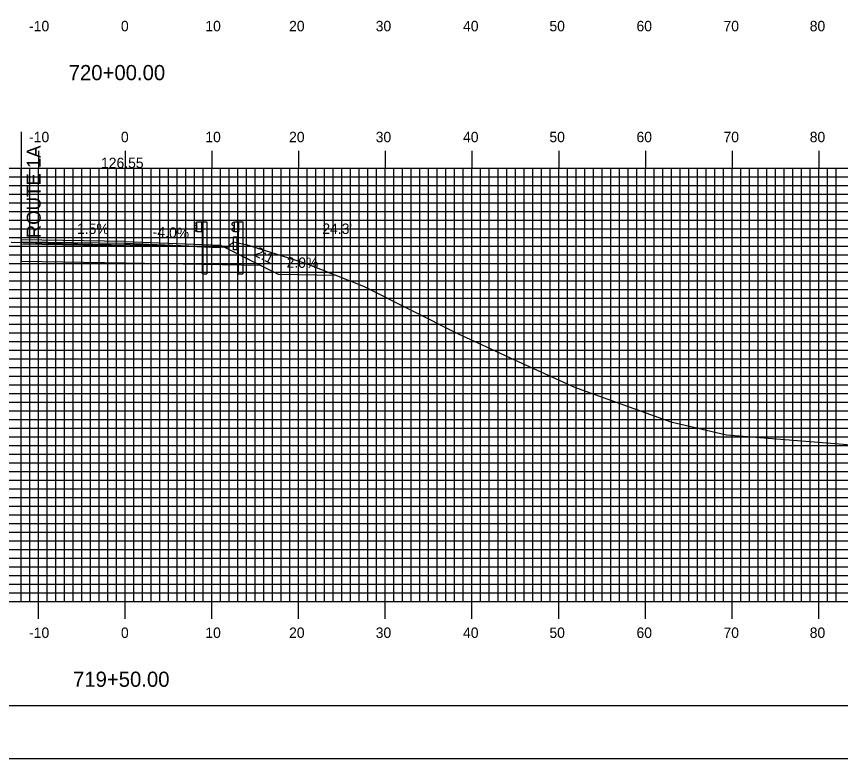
# Model space of a CAD drawing. Extents: x 858052 to 858395, y 364366 to 364586.
# Drawn here: x 858204.8 to 858299.9, y 364365.7 to 364451.3 of the extents above; entities that cross this region are included whole.
import ezdxf

# ---------------------------------------------------------------- set-up
doc = ezdxf.new("R2010")
doc.units = 0
for name, color, linetype in [('ANNOTATION', 7, 'Continuous'), ('BORDER', 7, 'Continuous'), ('D_Guardrail_Beam_Lt', 7, 'Continuous'), ('D_Roadway_Centerline', 7, 'Continuous'), ('D_Roadway_Centerline_Text', 7, 'Continuous'), ('D_Roadway_Edge_Shoulder', 7, 'Continuous'), ('D_Roadway_Edge_TW', 7, 'Continuous'), ('D_Roadway_Pavement', 7, 'Continuous'), ('D_Roadway_SlopeLines', 7, 'Continuous'), ('D_Roadway_SubGrade', 7, 'Continuous'), ('D_Text_Standard', 7, 'Continuous'), ('H_V ANNOTATION', 7, 'Continuous'), ('MAJOR', 7, 'Continuous'), ('MINOR', 7, 'Continuous'), ('PLOT BOUNDARY', 7, 'Continuous'), ('S_Curb_Type_1', 7, 'Continuous'), ('S_Guardrail_Beam', 7, 'Continuous'), ('S_Roadway_Centerline', 7, 'Continuous')]:
    doc.layers.add(name, color=color, linetype=linetype)

msp = doc.modelspace()

# ---------------------------------------------------------------- linework, layer by layer
at = {"layer": 'BORDER'}
msp.add_lwpolyline([(858067.762, 364371.787), (858387.762, 364371.787), (858387.762, 364581.787), (858067.762, 364581.787)], close=True, dxfattribs=at)
at = {"layer": 'D_Guardrail_Beam_Lt'}
for p, q in [((858225.542, 364427.494), (858225.399, 364427.394)), ((858225.399, 364427.251), (858225.594, 364427.115)), ((858225.594, 364426.916), (858225.399, 364426.78)), ((858225.632, 364427.516), (858225.558, 364427.501)), ((858225.628, 364427.051), (858225.628, 364426.98)), ((858225.632, 364427.599), (858226.32, 364427.599)), ((858225.632, 364426.432), (858225.632, 364427.599)), ((858226.153, 364427.599), (858226.153, 364426.432)), ((858226.257, 364427.599), (858226.257, 364426.432)), ((858226.32, 364427.599), (858226.791, 364427.599)), ((858226.32, 364427.599), (858226.32, 364426.432)), ((858226.791, 364427.599), (858226.791, 364421.599)), ((858225.399, 364426.637), (858225.542, 364426.537)), ((858225.558, 364426.53), (858225.632, 364426.516)), ((858226.32, 364426.432), (858225.632, 364426.432)), ((858226.299, 364421.599), (858226.299, 364426.432)), ((858226.299, 364421.599), (858226.791, 364421.599))]:
    msp.add_line(p, q, dxfattribs=at)
for centre, major_axis, start_param, end_param in [((858225.449, 364427.323), (-0.0877, 0), 5.323254, 7.243116), ((858225.449, 364426.708), (-0.0877, 0), 5.323254, 7.243116), ((858225.566, 364427.46), (-0.0417, 0), 4.907132, 5.323254), ((858225.549, 364427.051), (0.0789, 0), 0, 0.959931), ((858225.549, 364426.98), (0.0789, 0), 5.323254, 6.283185), ((858225.566, 364426.571), (-0.0417, 0), 0.959931, 1.376053)]:
    msp.add_ellipse(centre, major_axis=major_axis, ratio=0.995501, start_param=start_param, end_param=end_param, dxfattribs=at)
at = {"layer": 'D_Roadway_Centerline'}
for p, q in [((858217.362, 364425.336), (858205.362, 364425.516)), ((858217.362, 364425.086), (858205.362, 364425.266)), ((858217.362, 364424.839), (858205.362, 364425.019)), ((858217.362, 364422.836), (858205.362, 364423.016))]:
    msp.add_line(p, q, dxfattribs=at)
at = {"layer": 'D_Roadway_Edge_Shoulder'}
for points in [[(858217.362, 364425.336), (858228.362, 364424.896), (858228.362, 364424.646), (858217.362, 364425.086)], [(858217.362, 364425.336), (858225.362, 364425.016), (858225.362, 364425.016), (858228.362, 364424.896), (858228.362, 364424.646), (858217.362, 364425.086)]]:
    msp.add_lwpolyline(points, close=True, dxfattribs=at)
at = {"layer": 'D_Roadway_Edge_TW'}
msp.add_line((858205.362, 364425.544), (858205.362, 364425.294), dxfattribs=at)
at = {"layer": 'D_Roadway_Pavement'}
msp.add_line((858205.362, 364425.294), (858205.362, 364425.044), dxfattribs=at)
msp.add_lwpolyline([(858217.362, 364425.086), (858217.362, 364424.836)], dxfattribs=at)
msp.add_lwpolyline([(858217.362, 364425.086), (858217.362, 364424.836)], dxfattribs=at)
msp.add_lwpolyline([(858217.362, 364425.086), (858217.362, 364424.836)], dxfattribs=at)
msp.add_lwpolyline([(858217.362, 364425.086), (858217.362, 364424.836)], dxfattribs=at)
at = {"layer": 'D_Roadway_SlopeLines'}
for points in [[(858228.362, 364424.896), (858235.026, 364421.563)], [(858235.026, 364421.563), (858241.686, 364421.43)]]:
    msp.add_lwpolyline(points, dxfattribs=at)
at = {"layer": 'D_Roadway_SubGrade'}
for p, q in [((858205.362, 364438.001), (858205.362, 364423.112)), ((858205.362, 364437.973), (858205.362, 364423.016)), ((858205.362, 364425.044), (858205.362, 364423.112))]:
    msp.add_line(p, q, dxfattribs=at)
msp.add_lwpolyline([(858217.362, 364424.836), (858217.362, 364425.086), (858228.362, 364424.646), (858228.362, 364424.896), (858233.026, 364422.563), (858217.362, 364422.836)], close=True, dxfattribs=at)
at = {"layer": 'MAJOR'}
for p, q in [((858207.362, 364435.791), (858207.362, 364433.787)), ((858217.362, 364435.791), (858217.362, 364433.787)), ((858227.362, 364435.791), (858227.362, 364433.787)), ((858237.362, 364435.791), (858237.362, 364433.787)), ((858247.362, 364435.791), (858247.362, 364433.787)), ((858257.362, 364435.791), (858257.362, 364433.787)), ((858267.362, 364435.791), (858267.362, 364433.787)), ((858277.362, 364435.791), (858277.362, 364433.787)), ((858287.362, 364435.791), (858287.362, 364433.787)), ((858297.362, 364435.791), (858297.362, 364433.787)), ((858077.362, 364433.787), (858357.362, 364433.787)), ((858077.362, 364433.787), (858357.362, 364433.787)), ((858207.362, 364383.787), (858207.362, 364433.787)), ((858217.362, 364383.787), (858217.362, 364433.787)), ((858227.362, 364383.787), (858227.362, 364433.787)), ((858237.362, 364383.787), (858237.362, 364433.787)), ((858247.362, 364383.787), (858247.362, 364433.787)), ((858257.362, 364383.787), (858257.362, 364433.787)), ((858267.362, 364383.787), (858267.362, 364433.787)), ((858277.362, 364383.787), (858277.362, 364433.787)), ((858287.362, 364383.787), (858287.362, 364433.787)), ((858297.362, 364383.787), (858297.362, 364433.787)), ((858077.362, 364428.787), (858357.362, 364428.787)), ((858077.362, 364423.787), (858357.362, 364423.787)), ((858077.362, 364418.787), (858357.362, 364418.787)), ((858077.362, 364413.787), (858357.362, 364413.787)), ((858077.362, 364408.787), (858357.362, 364408.787)), ((858077.362, 364403.787), (858357.362, 364403.787)), ((858077.362, 364398.787), (858357.362, 364398.787)), ((858077.362, 364393.787), (858357.362, 364393.787)), ((858077.362, 364388.787), (858357.362, 364388.787)), ((858077.362, 364383.787), (858357.362, 364383.787)), ((858077.362, 364383.787), (858357.362, 364383.787)), ((858207.362, 364381.783), (858207.362, 364383.787)), ((858217.362, 364381.783), (858217.362, 364383.787)), ((858227.362, 364381.783), (858227.362, 364383.787)), ((858237.362, 364381.783), (858237.362, 364383.787)), ((858247.362, 364381.783), (858247.362, 364383.787)), ((858257.362, 364381.783), (858257.362, 364383.787)), ((858267.362, 364381.783), (858267.362, 364383.787)), ((858277.362, 364381.783), (858277.362, 364383.787)), ((858287.362, 364381.783), (858287.362, 364383.787)), ((858297.362, 364381.783), (858297.362, 364383.787))]:
    msp.add_line(p, q, dxfattribs=at)
at = {"layer": 'MINOR'}
for p, q in [((858205.362, 364383.787), (858205.362, 364433.787)), ((858206.362, 364383.787), (858206.362, 364433.787)), ((858208.362, 364383.787), (858208.362, 364433.787)), ((858209.362, 364383.787), (858209.362, 364433.787)), ((858210.362, 364383.787), (858210.362, 364433.787)), ((858211.362, 364383.787), (858211.362, 364433.787)), ((858212.362, 364383.787), (858212.362, 364433.787)), ((858213.362, 364383.787), (858213.362, 364433.787)), ((858214.362, 364383.787), (858214.362, 364433.787)), ((858215.362, 364383.787), (858215.362, 364433.787)), ((858216.362, 364383.787), (858216.362, 364433.787)), ((858218.362, 364383.787), (858218.362, 364433.787)), ((858219.362, 364383.787), (858219.362, 364433.787)), ((858220.362, 364383.787), (858220.362, 364433.787)), ((858221.362, 364383.787), (858221.362, 364433.787)), ((858222.362, 364383.787), (858222.362, 364433.787)), ((858223.362, 364383.787), (858223.362, 364433.787)), ((858224.362, 364383.787), (858224.362, 364433.787)), ((858225.362, 364383.787), (858225.362, 364433.787)), ((858226.362, 364383.787), (858226.362, 364433.787)), ((858228.362, 364383.787), (858228.362, 364433.787)), ((858229.362, 364383.787), (858229.362, 364433.787)), ((858230.362, 364383.787), (858230.362, 364433.787)), ((858231.362, 364383.787), (858231.362, 364433.787)), ((858232.362, 364383.787), (858232.362, 364433.787)), ((858233.362, 364383.787), (858233.362, 364433.787)), ((858234.362, 364383.787), (858234.362, 364433.787)), ((858235.362, 364383.787), (858235.362, 364433.787)), ((858236.362, 364383.787), (858236.362, 364433.787)), ((858238.362, 364383.787), (858238.362, 364433.787)), ((858239.362, 364383.787), (858239.362, 364433.787)), ((858240.362, 364383.787), (858240.362, 364433.787)), ((858241.362, 364383.787), (858241.362, 364433.787)), ((858242.362, 364383.787), (858242.362, 364433.787)), ((858243.362, 364383.787), (858243.362, 364433.787)), ((858244.362, 364383.787), (858244.362, 364433.787)), ((858245.362, 364383.787), (858245.362, 364433.787)), ((858246.362, 364383.787), (858246.362, 364433.787)), ((858248.362, 364383.787), (858248.362, 364433.787)), ((858249.362, 364383.787), (858249.362, 364433.787)), ((858250.362, 364383.787), (858250.362, 364433.787)), ((858251.362, 364383.787), (858251.362, 364433.787)), ((858252.362, 364383.787), (858252.362, 364433.787)), ((858253.362, 364383.787), (858253.362, 364433.787)), ((858254.362, 364383.787), (858254.362, 364433.787)), ((858255.362, 364383.787), (858255.362, 364433.787)), ((858256.362, 364383.787), (858256.362, 364433.787)), ((858258.362, 364383.787), (858258.362, 364433.787)), ((858259.362, 364383.787), (858259.362, 364433.787)), ((858260.362, 364383.787), (858260.362, 364433.787)), ((858261.362, 364383.787), (858261.362, 364433.787)), ((858262.362, 364383.787), (858262.362, 364433.787)), ((858263.362, 364383.787), (858263.362, 364433.787)), ((858264.362, 364383.787), (858264.362, 364433.787)), ((858265.362, 364383.787), (858265.362, 364433.787)), ((858266.362, 364383.787), (858266.362, 364433.787)), ((858268.362, 364383.787), (858268.362, 364433.787)), ((858269.362, 364383.787), (858269.362, 364433.787)), ((858270.362, 364383.787), (858270.362, 364433.787)), ((858271.362, 364383.787), (858271.362, 364433.787)), ((858272.362, 364383.787), (858272.362, 364433.787)), ((858273.362, 364383.787), (858273.362, 364433.787)), ((858274.362, 364383.787), (858274.362, 364433.787)), ((858275.362, 364383.787), (858275.362, 364433.787)), ((858276.362, 364383.787), (858276.362, 364433.787)), ((858278.362, 364383.787), (858278.362, 364433.787)), ((858279.362, 364383.787), (858279.362, 364433.787)), ((858280.362, 364383.787), (858280.362, 364433.787)), ((858281.362, 364383.787), (858281.362, 364433.787)), ((858282.362, 364383.787), (858282.362, 364433.787)), ((858283.362, 364383.787), (858283.362, 364433.787)), ((858284.362, 364383.787), (858284.362, 364433.787)), ((858285.362, 364383.787), (858285.362, 364433.787)), ((858286.362, 364383.787), (858286.362, 364433.787)), ((858288.362, 364383.787), (858288.362, 364433.787)), ((858289.362, 364383.787), (858289.362, 364433.787)), ((858290.362, 364383.787), (858290.362, 364433.787)), ((858291.362, 364383.787), (858291.362, 364433.787)), ((858292.362, 364383.787), (858292.362, 364433.787)), ((858293.362, 364383.787), (858293.362, 364433.787)), ((858294.362, 364383.787), (858294.362, 364433.787)), ((858295.362, 364383.787), (858295.362, 364433.787)), ((858296.362, 364383.787), (858296.362, 364433.787)), ((858298.362, 364383.787), (858298.362, 364433.787)), ((858299.362, 364383.787), (858299.362, 364433.787)), ((858077.362, 364432.787), (858357.362, 364432.787)), ((858077.362, 364431.787), (858357.362, 364431.787)), ((858077.362, 364430.787), (858357.362, 364430.787)), ((858077.362, 364429.787), (858357.362, 364429.787)), ((858077.362, 364427.787), (858357.362, 364427.787)), ((858077.362, 364426.787), (858357.362, 364426.787)), ((858077.362, 364425.787), (858357.362, 364425.787)), ((858077.362, 364424.787), (858357.362, 364424.787)), ((858077.362, 364422.787), (858357.362, 364422.787)), ((858077.362, 364421.787), (858357.362, 364421.787)), ((858077.362, 364420.787), (858357.362, 364420.787)), ((858077.362, 364419.787), (858357.362, 364419.787)), ((858077.362, 364417.787), (858357.362, 364417.787)), ((858077.362, 364416.787), (858357.362, 364416.787)), ((858077.362, 364415.787), (858357.362, 364415.787)), ((858077.362, 364414.787), (858357.362, 364414.787)), ((858077.362, 364412.787), (858357.362, 364412.787)), ((858077.362, 364411.787), (858357.362, 364411.787)), ((858077.362, 364410.787), (858357.362, 364410.787)), ((858077.362, 364409.787), (858357.362, 364409.787)), ((858077.362, 364407.787), (858357.362, 364407.787)), ((858077.362, 364406.787), (858357.362, 364406.787)), ((858077.362, 364405.787), (858357.362, 364405.787)), ((858077.362, 364404.787), (858357.362, 364404.787)), ((858077.362, 364402.787), (858357.362, 364402.787)), ((858077.362, 364401.787), (858357.362, 364401.787)), ((858077.362, 364400.787), (858357.362, 364400.787)), ((858077.362, 364399.787), (858357.362, 364399.787)), ((858077.362, 364397.787), (858357.362, 364397.787)), ((858077.362, 364396.787), (858357.362, 364396.787)), ((858077.362, 364395.787), (858357.362, 364395.787)), ((858077.362, 364394.787), (858357.362, 364394.787)), ((858077.362, 364392.787), (858357.362, 364392.787)), ((858077.362, 364391.787), (858357.362, 364391.787)), ((858077.362, 364390.787), (858357.362, 364390.787)), ((858077.362, 364389.787), (858357.362, 364389.787)), ((858077.362, 364387.787), (858357.362, 364387.787)), ((858077.362, 364386.787), (858357.362, 364386.787)), ((858077.362, 364385.787), (858357.362, 364385.787)), ((858077.362, 364384.787), (858357.362, 364384.787))]:
    msp.add_line(p, q, dxfattribs=at)
at = {"layer": 'PLOT BOUNDARY'}
msp.add_lwpolyline([(858051.575, 364365.669), (858391.575, 364365.669), (858391.575, 364585.669), (858051.575, 364585.669)], close=True, dxfattribs=at)
at = {"layer": 'S_Curb_Type_1'}
msp.add_lwpolyline([(858229.844, 364425.865), (858230.261, 364425.865), (858230.261, 364424.365), (858229.844, 364424.365)], close=True, dxfattribs=at)
msp.add_lwpolyline([(858229.844, 364425.865), (858230.261, 364425.865), (858230.261, 364424.365), (858229.844, 364424.365)], close=True, dxfattribs=at)
at = {"layer": 'S_Guardrail_Beam'}
for p, q in [((858229.858, 364427.504), (858229.714, 364427.404)), ((858229.858, 364427.504), (858229.714, 364427.404)), ((858229.714, 364427.261), (858229.909, 364427.125)), ((858229.714, 364427.261), (858229.909, 364427.125)), ((858229.909, 364426.905), (858229.714, 364426.769)), ((858229.909, 364426.905), (858229.714, 364426.769)), ((858229.956, 364427.526), (858229.874, 364427.511)), ((858229.956, 364427.526), (858229.874, 364427.511)), ((858229.943, 364427.061), (858229.943, 364426.97)), ((858229.943, 364427.061), (858229.943, 364426.97)), ((858229.956, 364427.599), (858230.446, 364427.599)), ((858229.956, 364426.432), (858229.956, 364427.599)), ((858229.956, 364427.599), (858230.446, 364427.599)), ((858229.956, 364426.432), (858229.956, 364427.599)), ((858230.446, 364427.599), (858230.938, 364427.599)), ((858230.446, 364427.599), (858230.446, 364426.432)), ((858230.446, 364427.599), (858230.938, 364427.599)), ((858230.446, 364427.599), (858230.446, 364426.432)), ((858230.938, 364427.599), (858230.938, 364421.599)), ((858230.938, 364427.599), (858230.938, 364421.599)), ((858229.714, 364426.626), (858229.858, 364426.526)), ((858229.714, 364426.626), (858229.858, 364426.526)), ((858229.874, 364426.519), (858229.956, 364426.505)), ((858229.874, 364426.519), (858229.956, 364426.505)), ((858230.446, 364426.432), (858229.956, 364426.432)), ((858230.446, 364426.432), (858229.956, 364426.432)), ((858230.446, 364421.599), (858230.446, 364426.432)), ((858230.446, 364421.599), (858230.446, 364426.432)), ((858230.446, 364421.599), (858230.938, 364421.599)), ((858230.446, 364421.599), (858230.938, 364421.599))]:
    msp.add_line(p, q, dxfattribs=at)
for centre, major_axis, start_param, end_param in [((858229.764, 364427.333), (-0.0877, 0), 5.323254, 7.243116), ((858229.764, 364427.333), (-0.0877, 0), 5.323254, 7.243116), ((858229.764, 364426.698), (-0.0877, 0), 5.323254, 7.243116), ((858229.764, 364426.698), (-0.0877, 0), 5.323254, 7.243116), ((858229.881, 364427.47), (-0.0417, 0), 4.886922, 5.323254), ((858229.881, 364427.47), (-0.0417, 0), 4.886922, 5.323254), ((858229.864, 364427.061), (0.0789, 0), 0, 0.959931), ((858229.864, 364427.061), (0.0789, 0), 0, 0.959931), ((858229.864, 364426.97), (0.0789, 0), 5.323254, 6.283185), ((858229.864, 364426.97), (0.0789, 0), 5.323254, 6.283185), ((858229.881, 364426.56), (-0.0417, 0), 0.959931, 1.396263), ((858229.881, 364426.56), (-0.0417, 0), 0.959931, 1.396263)]:
    msp.add_ellipse(centre, major_axis=major_axis, ratio=0.995501, start_param=start_param, end_param=end_param, dxfattribs=at)
at = {"layer": 'S_Roadway_Centerline'}
msp.add_lwpolyline([(858204.219, 364425.233), (858208.402, 364425.14), (858213.589, 364425.039), (858222.297, 364424.871), (858223.57, 364424.827), (858229.199, 364424.667), (858229.345, 364424.81), (858229.844, 364425.281), (858230.912, 364425.059), (858231.305, 364424.964), (858236.92, 364423.207), (858238.221, 364422.799), (858244.848, 364420.181), (858255.752, 364414.663), (858258.54, 364413.408), (858262.246, 364411.671), (858269.203, 364408.507), (858280.301, 364404.507), (858286.703, 364403.02), (858300.682, 364401.923)], dxfattribs=at)

# ---------------------------------------------------------------- texts
at = {"layer": 'ANNOTATION'}
for s, height, rotation, p in [('ROUTE 1A', 1.6, 90, (858207.622, 364425.707)), ('1.5%', 1.2, 359.41462, (858211.813, 364426.214)), ('-4.0%', 1.2, 357.70939, (858220.531, 364425.845)), ('2:1', 1.2, 333.43495, (858232.144, 364423.713)), ('-2.0%', 1.2, 358.85424, (858235.439, 364422.331))]:
    msp.add_text(s, height=height, rotation=rotation, dxfattribs=at).set_placement(p)
at = {"layer": 'D_Roadway_Centerline_Text'}
msp.add_text('126.55', height=1.2, dxfattribs=at).set_placement((858214.584, 364433.798))
at = {"layer": 'D_Text_Standard'}
msp.add_text("24.3'", height=1.2, dxfattribs=at).set_placement((858240.106, 364426.203))
at = {"layer": 'H_V ANNOTATION'}
for s, height, p in [('-10', 1.2, (858206.291, 364449.587)), ('0', 1.2, (858216.88, 364449.587)), ('10', 1.2, (858226.612, 364449.587)), ('20', 1.2, (858236.27, 364449.587)), ('30', 1.2, (858246.259, 364449.587)), ('40', 1.2, (858256.334, 364449.587)), ('50', 1.2, (858266.291, 364449.587)), ('60', 1.2, (858276.334, 364449.587)), ('70', 1.2, (858286.366, 364449.587)), ('80', 1.2, (858296.312, 364449.587)), ('720+00.00', 1.75, (858210.853, 364443.943)), ('-10', 1.2, (858206.291, 364436.787)), ('0', 1.2, (858216.88, 364436.787)), ('10', 1.2, (858226.612, 364436.787)), ('20', 1.2, (858236.27, 364436.787)), ('30', 1.2, (858246.259, 364436.787)), ('40', 1.2, (858256.334, 364436.787)), ('50', 1.2, (858266.291, 364436.787)), ('60', 1.2, (858276.334, 364436.787)), ('70', 1.2, (858286.366, 364436.787)), ('80', 1.2, (858296.312, 364436.787)), ('-10', 1.2, (858206.291, 364379.587)), ('0', 1.2, (858216.88, 364379.587)), ('10', 1.2, (858226.612, 364379.587)), ('20', 1.2, (858236.27, 364379.587)), ('30', 1.2, (858246.259, 364379.587)), ('40', 1.2, (858256.334, 364379.587)), ('50', 1.2, (858266.291, 364379.587)), ('60', 1.2, (858276.334, 364379.587)), ('70', 1.2, (858286.366, 364379.587)), ('80', 1.2, (858296.312, 364379.587)), ('719+50.00', 1.75, (858211.353, 364373.943))]:
    msp.add_text(s, height=height, dxfattribs=at).set_placement(p)

doc.saveas('drawing.dxf')
